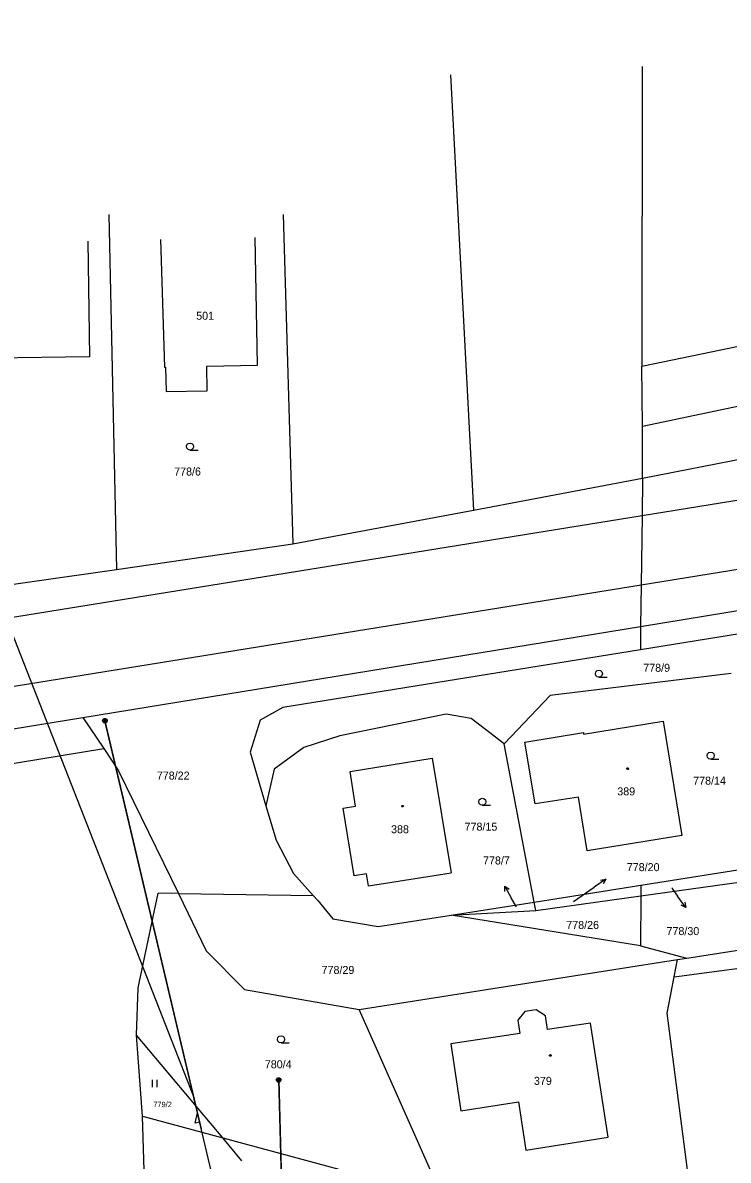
# Model space of a CAD drawing. Extents: x -747792 to -745414, y -1093712 to -1091463.
# Drawn here: x -746034.4 to -745959.5, y -1091645.8 to -1091524.9 of the extents above; entities that cross this region are included whole.
import ezdxf

# ---------------------------------------------------------------- set-up
doc = ezdxf.new("R2010")
doc.units = 0
for name, color, linetype in [('Pracovní_bod JDTM STC_VC', 7, 'Continuous'), ('Pracovní_bod JDTM STC_VC - výška', 7, 'Continuous'), ('Pracovní_bod JDTM STC_VC - číslo', 7, 'Continuous'), ('Pracovní_bod NN - výška', 7, 'Continuous'), ('Pracovní_bod polohopisu', 7, 'Continuous'), ('Pracovní_bod polohopisu - výška', 7, 'Continuous'), ('Pracovní_bod polohopisu - číslo', 7, 'Continuous')]:
    doc.layers.add(name, color=color, linetype=linetype)

msp = doc.modelspace()

# ---------------------------------------------------------------- linework, layer by layer
at = {"layer": 'Pracovní_bod JDTM STC_VC - výška'}
for points in [[(-745970.17, -1091604.08), (-745970.12, -1091604.09), (-745970.09, -1091604.14), (-745970.08, -1091604.17), (-745970.09, -1091604.21), (-745970.14, -1091604.25), (-745970.17, -1091604.26), (-745970.22, -1091604.24), (-745970.25, -1091604.21), (-745970.26, -1091604.17), (-745970.25, -1091604.12), (-745970.21, -1091604.09)], [(-745994.09, -1091608.07), (-745994.04, -1091608.08), (-745994.01, -1091608.13), (-745994, -1091608.16), (-745994.01, -1091608.21), (-745994.05, -1091608.24), (-745994.09, -1091608.24), (-745994.14, -1091608.23), (-745994.17, -1091608.2), (-745994.18, -1091608.16), (-745994.17, -1091608.11), (-745994.12, -1091608.08)], [(-745978.39, -1091634.55), (-745978.34, -1091634.56), (-745978.32, -1091634.61), (-745978.3, -1091634.64), (-745978.32, -1091634.69), (-745978.35, -1091634.72), (-745978.39, -1091634.72), (-745978.44, -1091634.71), (-745978.47, -1091634.68), (-745978.48, -1091634.64), (-745978.47, -1091634.59), (-745978.43, -1091634.56)]]:
    msp.add_lwpolyline(points, close=True, dxfattribs=at)
at = {"layer": 'Pracovní_bod JDTM STC_VC - číslo'}
for points in [[(-746016.66, -1091570.33), (-746016.85, -1091570.28), (-746016.99, -1091570.14), (-746017.04, -1091569.96), (-746016.99, -1091569.77), (-746016.85, -1091569.63), (-746016.66, -1091569.58), (-746016.47, -1091569.63), (-746016.33, -1091569.77), (-746016.29, -1091569.96), (-746016.33, -1091570.14), (-746016.47, -1091570.28), (-746016.66, -1091570.33), (-746015.79, -1091570.33)], [(-745973.24, -1091594.46), (-745973.43, -1091594.41), (-745973.57, -1091594.27), (-745973.61, -1091594.08), (-745973.57, -1091593.9), (-745973.43, -1091593.76), (-745973.24, -1091593.71), (-745973.05, -1091593.76), (-745972.92, -1091593.9), (-745972.86, -1091594.08), (-745972.92, -1091594.27), (-745973.05, -1091594.41), (-745973.24, -1091594.46), (-745972.36, -1091594.46)], [(-745961.36, -1091603.17), (-745961.55, -1091603.12), (-745961.69, -1091602.98), (-745961.73, -1091602.79), (-745961.69, -1091602.61), (-745961.55, -1091602.47), (-745961.36, -1091602.42), (-745961.17, -1091602.47), (-745961.03, -1091602.61), (-745960.98, -1091602.79), (-745961.03, -1091602.98), (-745961.17, -1091603.12), (-745961.36, -1091603.17), (-745960.48, -1091603.17)], [(-745985.62, -1091608.06), (-745985.81, -1091608.01), (-745985.95, -1091607.87), (-745985.99, -1091607.69), (-745985.95, -1091607.5), (-745985.81, -1091607.36), (-745985.62, -1091607.31), (-745985.43, -1091607.36), (-745985.29, -1091607.5), (-745985.24, -1091607.69), (-745985.29, -1091607.87), (-745985.43, -1091608.01), (-745985.62, -1091608.06), (-745984.74, -1091608.06)], [(-746007, -1091633.3), (-746007.19, -1091633.25), (-746007.33, -1091633.11), (-746007.38, -1091632.93), (-746007.33, -1091632.74), (-746007.19, -1091632.6), (-746007, -1091632.55), (-746006.81, -1091632.6), (-746006.68, -1091632.74), (-746006.62, -1091632.93), (-746006.68, -1091633.11), (-746006.81, -1091633.25), (-746007, -1091633.3), (-746006.12, -1091633.3)], [(-746020.67, -1091637.24), (-746020.67, -1091637.99)], [(-746020.17, -1091637.99), (-746020.17, -1091637.24)]]:
    msp.add_lwpolyline(points, dxfattribs=at)
at = {"layer": 'Pracovní_bod NN - výška'}
for points in [[(-745968.62, -1091529.58), (-745968.67, -1091561.42)], [(-745988.98, -1091530.48), (-745986.57, -1091576.7)], [(-746025.3, -1091545.31), (-746024.48, -1091583)], [(-746006.76, -1091545.31), (-746005.74, -1091580.3)], [(-746027.53, -1091548.13), (-746027.36, -1091560.41)], [(-746019.81, -1091547.95), (-746019.38, -1091561.53)], [(-746009.49, -1091561.3), (-746009.75, -1091547.74)], [(-745968.67, -1091561.42), (-745924.84, -1091552.35)], [(-745968.61, -1091567.78), (-745924.3, -1091558.46)], [(-746027.36, -1091560.41), (-746037.54, -1091560.55)], [(-746019.38, -1091561.53), (-746019.27, -1091561.52)], [(-746019.27, -1091561.52), (-746019.2, -1091564.11)], [(-746014.88, -1091561.41), (-746009.49, -1091561.3)], [(-746014.83, -1091564.03), (-746014.88, -1091561.41)], [(-745968.61, -1091567.78), (-745968.67, -1091561.42)], [(-746019.2, -1091564.11), (-746014.83, -1091564.03)], [(-745968.6, -1091573.31), (-745923.7, -1091564.54)], [(-745968.6, -1091573.31), (-745968.61, -1091567.78)], [(-745986.57, -1091576.7), (-745968.6, -1091573.31)], [(-745968.6, -1091573.31), (-745968.65, -1091577.3)], [(-746005.74, -1091580.3), (-745986.57, -1091576.7)], [(-745968.65, -1091577.3), (-745968.74, -1091584.63)], [(-746024.48, -1091583), (-746005.74, -1091580.3)], [(-746051.14, -1091586.81), (-746024.48, -1091583)], [(-745968.74, -1091584.63), (-745968.8, -1091589.06)], [(-745968.8, -1091589.06), (-745945.53, -1091585.26)], [(-745945.58, -1091587.8), (-745968.83, -1091591.55)], [(-746028.05, -1091598.72), (-745968.8, -1091589.06)], [(-745968.8, -1091589.06), (-745968.83, -1091591.55)], [(-745968.83, -1091591.55), (-746006.8, -1091597.68)], [(-745959.19, -1091594.06), (-745978.41, -1091596.41)], [(-745978.41, -1091596.41), (-745983.31, -1091601.54)], [(-746006.8, -1091597.68), (-746009.21, -1091599.02)], [(-746046.56, -1091601.74), (-746028.05, -1091598.72)], [(-746028.05, -1091598.72), (-746025.82, -1091602.04)], [(-746009.21, -1091599.02), (-746010.28, -1091602.42)], [(-745989.44, -1091598.37), (-746000.77, -1091600.68)], [(-745986.8, -1091598.84), (-745989.44, -1091598.37)], [(-745983.31, -1091601.54), (-745986.8, -1091598.84)], [(-745974.86, -1091600.51), (-745966.39, -1091599.13)], [(-745966.39, -1091599.13), (-745964.41, -1091611.26)], [(-745981.09, -1091601.36), (-745974.88, -1091600.33)], [(-745974.88, -1091600.33), (-745974.86, -1091600.51)], [(-746000.77, -1091600.68), (-746004.58, -1091601.91)], [(-745980.12, -1091618.34), (-745983.31, -1091601.54)], [(-745980.01, -1091607.91), (-745981.09, -1091601.36)], [(-746041.61, -1091604.62), (-746025.82, -1091602.04)], [(-746025.82, -1091602.04), (-746024.25, -1091604.39)], [(-746010.28, -1091602.42), (-746008.61, -1091608.11)], [(-746004.58, -1091601.91), (-746007.72, -1091604.24)], [(-745999.67, -1091604.47), (-745990.93, -1091603.06)], [(-745990.93, -1091603.06), (-745988.93, -1091615.23)], [(-746024.25, -1091604.39), (-746017.9, -1091617.43)], [(-746007.72, -1091604.24), (-746008.61, -1091608.11)], [(-745999.08, -1091608.14), (-745999.67, -1091604.47)], [(-745975.4, -1091607.19), (-745980.01, -1091607.91)], [(-745974.48, -1091612.9), (-745975.4, -1091607.19)], [(-746008.61, -1091608.11), (-746007.53, -1091611.75)], [(-746000.41, -1091608.36), (-745999.08, -1091608.14)], [(-745999.24, -1091615.56), (-746000.41, -1091608.36)], [(-745964.41, -1091611.26), (-745974.48, -1091612.9)], [(-746007.53, -1091611.75), (-746005.66, -1091615.32)], [(-745968.77, -1091616.55), (-745955.77, -1091614.51)], [(-746005.66, -1091615.32), (-746003.57, -1091617.65)], [(-745997.91, -1091615.35), (-745999.24, -1091615.56)], [(-745997.7, -1091616.63), (-745997.91, -1091615.35)], [(-745997.7, -1091616.63), (-745988.93, -1091615.23)], [(-745968.78, -1091617.68), (-745955.54, -1091615.85)], [(-746022.18, -1091627.45), (-746020.05, -1091617.4)], [(-746017.9, -1091617.43), (-746020.05, -1091617.4)], [(-746017.9, -1091617.43), (-746003.57, -1091617.65)], [(-746017.9, -1091617.43), (-746014.94, -1091623.51)], [(-745980.12, -1091618.34), (-745968.77, -1091616.55)], [(-745968.77, -1091616.55), (-745968.78, -1091617.68)], [(-746003.57, -1091617.65), (-746003.09, -1091618.18)], [(-746003.09, -1091618.18), (-746001.49, -1091620.11)], [(-745988.92, -1091619.73), (-745980.12, -1091618.34)], [(-745979.95, -1091619.23), (-745980.12, -1091618.34)], [(-745979.95, -1091619.23), (-745968.78, -1091617.68)], [(-745968.78, -1091617.68), (-745968.83, -1091622.99)], [(-745996.67, -1091620.95), (-745988.92, -1091619.73)], [(-745988.92, -1091619.73), (-745979.95, -1091619.23)], [(-745968.83, -1091622.99), (-745988.92, -1091619.73)], [(-746001.49, -1091620.11), (-745996.67, -1091620.95)], [(-745963.91, -1091624.31), (-745946.44, -1091621.58)], [(-746014.94, -1091623.51), (-746010.87, -1091627.63)], [(-745968.83, -1091622.99), (-745963.91, -1091624.31)], [(-745965.23, -1091626.27), (-745941.81, -1091623.17)], [(-745998.7, -1091629.75), (-745964.87, -1091624.46)], [(-745965.23, -1091626.27), (-745964.87, -1091624.46)], [(-745964.87, -1091624.46), (-745963.91, -1091624.31)], [(-745965.97, -1091630.16), (-745965.23, -1091626.27)], [(-746022.34, -1091632.47), (-746022.18, -1091627.45)], [(-746010.87, -1091627.63), (-745998.7, -1091629.75)], [(-745989.84, -1091649.69), (-745998.7, -1091629.75)], [(-745981.09, -1091629.96), (-745981.83, -1091630.88)], [(-745979.89, -1091629.78), (-745981.09, -1091629.96)], [(-745978.92, -1091630.43), (-745979.89, -1091629.78)], [(-745978.71, -1091631.88), (-745978.92, -1091630.43)], [(-745963.48, -1091649.5), (-745965.97, -1091630.16)], [(-745981.83, -1091630.88), (-745981.63, -1091632.31)], [(-745974.14, -1091631.2), (-745978.71, -1091631.88)], [(-745972.25, -1091643.33), (-745974.14, -1091631.2)], [(-746021.73, -1091641.08), (-746022.34, -1091632.47)], [(-746013.19, -1091643.39), (-746022.34, -1091632.47)], [(-745981.63, -1091632.31), (-745988.95, -1091633.4)], [(-745988.95, -1091633.4), (-745987.89, -1091640.51)], [(-745987.89, -1091640.51), (-745981.76, -1091639.58)], [(-745981.76, -1091639.58), (-745980.99, -1091644.7)], [(-746021.37, -1091652.64), (-746021.73, -1091641.08)], [(-746021.73, -1091641.08), (-746013.19, -1091643.39)], [(-746013.19, -1091643.39), (-745989.84, -1091649.69)], [(-746011.15, -1091645.82), (-746013.19, -1091643.39)], [(-745980.99, -1091644.7), (-745972.25, -1091643.33)]]:
    msp.add_lwpolyline(points, dxfattribs=at)
at = {"layer": 'Pracovní_bod polohopisu'}
for points in [[(-745893.77, -1091565.21), (-745968.65, -1091577.3)], [(-745968.74, -1091584.63), (-745898.24, -1091573.24)], [(-745968.65, -1091577.3), (-746050.02, -1091590.45)], [(-746047.89, -1091597.41), (-745968.74, -1091584.63)]]:
    msp.add_lwpolyline(points, dxfattribs=at)
at = {"layer": 'Pracovní_bod polohopisu - výška'}
for points in [[(-745972.51, -1091615.92), (-745973.74, -1091616.77)], [(-745973.06, -1091616), (-745972.51, -1091615.92), (-745972.78, -1091616.41)], [(-745983.24, -1091616.65), (-745982.5, -1091617.95)], [(-745983.21, -1091617.21), (-745983.24, -1091616.65), (-745982.78, -1091616.96)], [(-745975.92, -1091618.28), (-745973.74, -1091616.77)], [(-745965.49, -1091616.85), (-745964.88, -1091617.7)], [(-745981.99, -1091618.85), (-745982.5, -1091617.95)], [(-745964.01, -1091618.92), (-745964.88, -1091617.7)], [(-745964.09, -1091618.37), (-745964.01, -1091618.92), (-745964.5, -1091618.66)]]:
    msp.add_lwpolyline(points, dxfattribs=at)
at = {"layer": 'Pracovní_bod polohopisu - číslo'}
for points in [[(-746016.27, -1091639.04), (-746060.98, -1091524.93), (-746037.99, -1091583.61)], [(-746025.78, -1091598.84), (-746025.63, -1091598.84), (-746025.5, -1091598.93), (-746025.45, -1091599.08), (-746025.5, -1091599.22), (-746025.63, -1091599.31), (-746025.78, -1091599.31), (-746025.91, -1091599.22), (-746025.96, -1091599.08), (-746025.91, -1091598.93), (-746025.78, -1091598.84), (-746025.77, -1091598.86), (-746025.65, -1091598.86), (-746025.57, -1091598.9), (-746025.85, -1091598.9), (-746025.89, -1091598.94), (-746025.53, -1091598.94), (-746025.53, -1091598.98), (-746025.89, -1091598.98), (-746025.91, -1091599.02), (-746025.51, -1091599.02), (-746025.49, -1091599.06), (-746025.93, -1091599.06), (-746025.93, -1091599.1), (-746025.49, -1091599.1), (-746025.5, -1091599.14), (-746025.91, -1091599.14), (-746025.91, -1091599.18), (-746025.5, -1091599.18), (-746025.52, -1091599.22), (-746025.89, -1091599.22), (-746025.84, -1091599.26), (-746025.57, -1091599.26), (-746025.62, -1091599.3), (-746025.79, -1091599.3)], [(-746006.03, -1091682.4), (-746025.71, -1091599.08), (-746015.47, -1091642.44)], [(-746007.33, -1091637), (-746007.17, -1091637), (-746007.04, -1091637.09), (-746006.99, -1091637.23), (-746007.04, -1091637.38), (-746007.17, -1091637.47), (-746007.33, -1091637.47), (-746007.45, -1091637.38), (-746007.5, -1091637.23), (-746007.45, -1091637.09), (-746007.33, -1091637), (-746007.31, -1091637.02), (-746007.19, -1091637.02), (-746007.11, -1091637.06), (-746007.39, -1091637.06), (-746007.43, -1091637.1), (-746007.07, -1091637.1), (-746007.07, -1091637.14), (-746007.43, -1091637.14), (-746007.45, -1091637.18), (-746007.05, -1091637.18), (-746007.03, -1091637.22), (-746007.47, -1091637.22), (-746007.47, -1091637.26), (-746007.03, -1091637.26), (-746007.04, -1091637.3), (-746007.45, -1091637.3), (-746007.45, -1091637.34), (-746007.04, -1091637.34), (-746007.07, -1091637.38), (-746007.43, -1091637.38), (-746007.39, -1091637.42), (-746007.1, -1091637.42), (-746007.16, -1091637.46), (-746007.33, -1091637.46)], [(-746004.72, -1091731.06), (-746007.25, -1091637.24), (-746005.94, -1091685.9)], [(-746015.53, -1091642.2), (-746015.64, -1091641.71), (-746016.13, -1091641.83), (-746015.87, -1091640.74), (-746016.22, -1091639.28)]]:
    msp.add_lwpolyline(points, dxfattribs=at)

# ---------------------------------------------------------------- texts
at = {"layer": 'Pracovní_bod JDTM STC_VC'}
for s, height, p in [('501', 0.85, (-746016.01, -1091556.48)), ('778/6', 0.85, (-746018.35, -1091573.03)), ('778/9', 0.85, (-745968.52, -1091593.88)), ('778/22', 0.85, (-746020.19, -1091605.33)), ('778/14', 0.85, (-745963.22, -1091605.87)), ('389', 0.85, (-745971.28, -1091607.01)), ('388', 0.85, (-745995.31, -1091611.03)), ('778/15', 0.85, (-745987.5, -1091610.76)), ('778/26', 0.85, (-745976.7, -1091621.2)), ('778/29', 0.85, (-746002.69, -1091625.98)), ('780/4', 0.85, (-746008.72, -1091636)), ('379', 0.85, (-745980.13, -1091637.76)), ('779/2', 0.57, (-746020.57, -1091640.13))]:
    msp.add_text(s, height=height, dxfattribs=at).set_placement(p)
for s, rotation, p in [('778/30', 10.0841, (-745965.61, -1091616.87)), ('778/20', 9.5111, (-745976.04, -1091618.3)), ('778/7', 6.9901, (-745982.09, -1091618.86))]:
    msp.add_text(s, height=0.05, rotation=rotation, dxfattribs=at).set_placement(p)
at = {"layer": 'Pracovní_bod polohopisu - výška'}
for s, p in [('778/7', (-745985.54, -1091614.35)), ('778/20', (-745970.27, -1091615.06)), ('778/30', (-745966.05, -1091621.85))]:
    msp.add_text(s, height=0.85, dxfattribs=at).set_placement(p)

doc.saveas('drawing.dxf')
